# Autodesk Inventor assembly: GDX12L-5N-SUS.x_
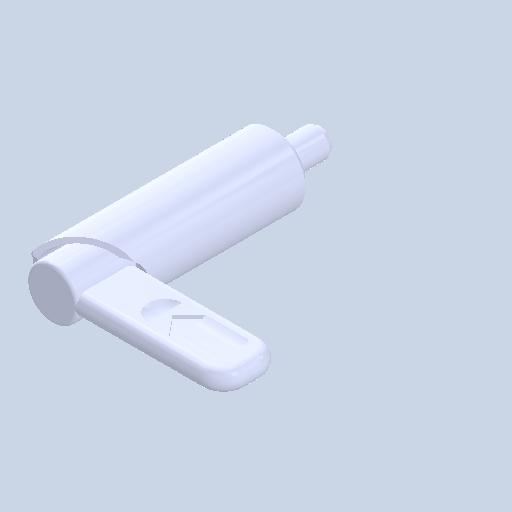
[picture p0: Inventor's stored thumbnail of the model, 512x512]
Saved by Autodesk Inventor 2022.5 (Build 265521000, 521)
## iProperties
Created: 2024-06
Part Number: GDX12L-5N-SUS.x_
Document SubType Name: Assembly
Designer: ImaoCorp
Author: ImaoCorp
Sending System: SOLIDWORKS 2022-2022290
MC: AMD64
MC_MODEL: Intel64 Family 6 Model 60 Stepping 3, GenuineIntel
OS: Windows_NT
FRU: Parasolid Version 33.1, build 260,  4-25-2022
FORMAT: text
GUISE: transmit
KEY: FILEGDX12L-5N-SUS.x_t
DATE: Wed Jun 12 09:31:42 2024
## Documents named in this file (3)
- Y:\5.更新分\2024年対応\xxxx_GDX\データ_imao品番\gdx12l-5n-sus\GDX12L-5N-SUS.x_.iam
- Y:\5.更新分\2024年対応\xxxx_GDX\データ_imao品番\gdx12l-5n-sus\GDX12L-5N-SUS_01.ipt
- Y:\5.更新分\2024年対応\xxxx_GDX\データ_imao品番\gdx12l-5n-sus\GDX12L-5N-SUS_02.ipt
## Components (2 placed, 2 different names)
1. GDX12L-5N-SUS_01
2. GDX12L-5N-SUS_02
